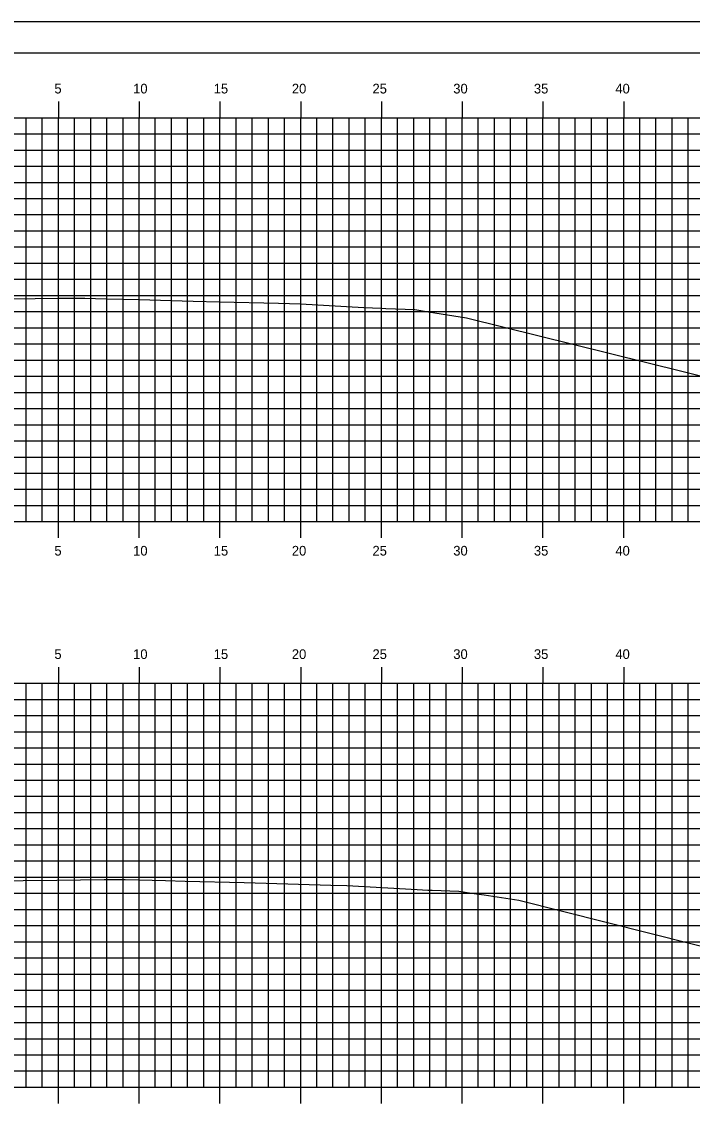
# Model space of a CAD drawing. Extents: x 1160718 to 1173142, y 616002 to 617630.
# Drawn here: x 1171295.7 to 1171337.2, y 616656.7 to 616723.9 of the extents above; entities that cross this region are included whole.
import ezdxf

# ---------------------------------------------------------------- set-up
doc = ezdxf.new("R2010")
doc.units = 0
for name, color, linetype in [('BORDER', 7, 'Continuous'), ('D_Roadway_SlopeLines', 7, 'Continuous'), ('H_V ANNOTATION', 7, 'Continuous'), ('MAJOR', 7, 'Continuous'), ('MINOR', 7, 'Continuous'), ('PLOT BOUNDARY', 7, 'Continuous'), ('S_Roadway_Centerline', 7, 'Continuous')]:
    doc.layers.add(name, color=color, linetype=linetype)

msp = doc.modelspace()

# ---------------------------------------------------------------- linework, layer by layer
at = {"layer": 'BORDER'}
msp.add_line((1171377.933, 616721.928), (1171217.933, 616721.928), dxfattribs=at)
at = {"layer": 'D_Roadway_SlopeLines'}
for points in [[(1171311.933, 616706.453), (1171312.022, 616706.431)], [(1171311.933, 616670.541), (1171312.029, 616670.517)]]:
    msp.add_lwpolyline(points, dxfattribs=at)
at = {"layer": 'MAJOR'}
for p, q in [((1171297.933, 616718.93), (1171297.933, 616717.928)), ((1171302.933, 616718.93), (1171302.933, 616717.928)), ((1171307.933, 616718.93), (1171307.933, 616717.928)), ((1171312.933, 616718.93), (1171312.933, 616717.928)), ((1171317.933, 616718.93), (1171317.933, 616717.928)), ((1171322.933, 616718.93), (1171322.933, 616717.928)), ((1171327.933, 616718.93), (1171327.933, 616717.928)), ((1171332.933, 616718.93), (1171332.933, 616717.928)), ((1171222.933, 616717.928), (1171362.933, 616717.928)), ((1171222.933, 616717.928), (1171362.933, 616717.928)), ((1171297.933, 616692.928), (1171297.933, 616717.928)), ((1171302.933, 616692.928), (1171302.933, 616717.928)), ((1171307.933, 616692.928), (1171307.933, 616717.928)), ((1171312.933, 616692.928), (1171312.933, 616717.928)), ((1171317.933, 616692.928), (1171317.933, 616717.928)), ((1171322.933, 616692.928), (1171322.933, 616717.928)), ((1171327.933, 616692.928), (1171327.933, 616717.928)), ((1171332.933, 616692.928), (1171332.933, 616717.928)), ((1171222.933, 616712.928), (1171362.933, 616712.928)), ((1171222.933, 616707.928), (1171362.933, 616707.928)), ((1171222.933, 616702.928), (1171362.933, 616702.928)), ((1171222.933, 616697.928), (1171362.933, 616697.928)), ((1171222.933, 616692.928), (1171362.933, 616692.928)), ((1171222.933, 616692.928), (1171362.933, 616692.928)), ((1171297.933, 616691.926), (1171297.933, 616692.928)), ((1171302.933, 616691.926), (1171302.933, 616692.928)), ((1171307.933, 616691.926), (1171307.933, 616692.928)), ((1171312.933, 616691.926), (1171312.933, 616692.928)), ((1171317.933, 616691.926), (1171317.933, 616692.928)), ((1171322.933, 616691.926), (1171322.933, 616692.928)), ((1171327.933, 616691.926), (1171327.933, 616692.928)), ((1171332.933, 616691.926), (1171332.933, 616692.928)), ((1171297.933, 616683.93), (1171297.933, 616682.928)), ((1171302.933, 616683.93), (1171302.933, 616682.928)), ((1171307.933, 616683.93), (1171307.933, 616682.928)), ((1171312.933, 616683.93), (1171312.933, 616682.928)), ((1171317.933, 616683.93), (1171317.933, 616682.928)), ((1171322.933, 616683.93), (1171322.933, 616682.928)), ((1171327.933, 616683.93), (1171327.933, 616682.928)), ((1171332.933, 616683.93), (1171332.933, 616682.928)), ((1171222.933, 616682.928), (1171362.933, 616682.928)), ((1171222.933, 616682.928), (1171362.933, 616682.928)), ((1171297.933, 616657.928), (1171297.933, 616682.928)), ((1171302.933, 616657.928), (1171302.933, 616682.928)), ((1171307.933, 616657.928), (1171307.933, 616682.928)), ((1171312.933, 616657.928), (1171312.933, 616682.928)), ((1171317.933, 616657.928), (1171317.933, 616682.928)), ((1171322.933, 616657.928), (1171322.933, 616682.928)), ((1171327.933, 616657.928), (1171327.933, 616682.928)), ((1171332.933, 616657.928), (1171332.933, 616682.928)), ((1171222.933, 616677.928), (1171362.933, 616677.928)), ((1171222.933, 616672.928), (1171362.933, 616672.928)), ((1171222.933, 616667.928), (1171362.933, 616667.928)), ((1171222.933, 616662.928), (1171362.933, 616662.928)), ((1171222.933, 616657.928), (1171362.933, 616657.928)), ((1171222.933, 616657.928), (1171362.933, 616657.928)), ((1171297.933, 616656.926), (1171297.933, 616657.928)), ((1171302.933, 616656.926), (1171302.933, 616657.928)), ((1171307.933, 616656.926), (1171307.933, 616657.928)), ((1171312.933, 616656.926), (1171312.933, 616657.928)), ((1171317.933, 616656.926), (1171317.933, 616657.928)), ((1171322.933, 616656.926), (1171322.933, 616657.928)), ((1171327.933, 616656.926), (1171327.933, 616657.928)), ((1171332.933, 616656.926), (1171332.933, 616657.928))]:
    msp.add_line(p, q, dxfattribs=at)
at = {"layer": 'MINOR'}
for p, q in [((1171295.933, 616692.928), (1171295.933, 616717.928)), ((1171296.933, 616692.928), (1171296.933, 616717.928)), ((1171298.933, 616692.928), (1171298.933, 616717.928)), ((1171299.933, 616692.928), (1171299.933, 616717.928)), ((1171300.933, 616692.928), (1171300.933, 616717.928)), ((1171301.933, 616692.928), (1171301.933, 616717.928)), ((1171303.933, 616692.928), (1171303.933, 616717.928)), ((1171304.933, 616692.928), (1171304.933, 616717.928)), ((1171305.933, 616692.928), (1171305.933, 616717.928)), ((1171306.933, 616692.928), (1171306.933, 616717.928)), ((1171308.933, 616692.928), (1171308.933, 616717.928)), ((1171309.933, 616692.928), (1171309.933, 616717.928)), ((1171310.933, 616692.928), (1171310.933, 616717.928)), ((1171311.933, 616692.928), (1171311.933, 616717.928)), ((1171313.933, 616692.928), (1171313.933, 616717.928)), ((1171314.933, 616692.928), (1171314.933, 616717.928)), ((1171315.933, 616692.928), (1171315.933, 616717.928)), ((1171316.933, 616692.928), (1171316.933, 616717.928)), ((1171318.933, 616692.928), (1171318.933, 616717.928)), ((1171319.933, 616692.928), (1171319.933, 616717.928)), ((1171320.933, 616692.928), (1171320.933, 616717.928)), ((1171321.933, 616692.928), (1171321.933, 616717.928)), ((1171323.933, 616692.928), (1171323.933, 616717.928)), ((1171324.933, 616692.928), (1171324.933, 616717.928)), ((1171325.933, 616692.928), (1171325.933, 616717.928)), ((1171326.933, 616692.928), (1171326.933, 616717.928)), ((1171328.933, 616692.928), (1171328.933, 616717.928)), ((1171329.933, 616692.928), (1171329.933, 616717.928)), ((1171330.933, 616692.928), (1171330.933, 616717.928)), ((1171331.933, 616692.928), (1171331.933, 616717.928)), ((1171333.933, 616692.928), (1171333.933, 616717.928)), ((1171334.933, 616692.928), (1171334.933, 616717.928)), ((1171335.933, 616692.928), (1171335.933, 616717.928)), ((1171336.933, 616692.928), (1171336.933, 616717.928)), ((1171222.933, 616716.928), (1171362.933, 616716.928)), ((1171222.933, 616715.928), (1171362.933, 616715.928)), ((1171222.933, 616714.928), (1171362.933, 616714.928)), ((1171222.933, 616713.928), (1171362.933, 616713.928)), ((1171222.933, 616711.928), (1171362.933, 616711.928)), ((1171222.933, 616710.928), (1171362.933, 616710.928)), ((1171222.933, 616709.928), (1171362.933, 616709.928)), ((1171222.933, 616708.928), (1171362.933, 616708.928)), ((1171222.933, 616706.928), (1171362.933, 616706.928)), ((1171222.933, 616705.928), (1171362.933, 616705.928)), ((1171222.933, 616704.928), (1171362.933, 616704.928)), ((1171222.933, 616703.928), (1171362.933, 616703.928)), ((1171222.933, 616701.928), (1171362.933, 616701.928)), ((1171222.933, 616700.928), (1171362.933, 616700.928)), ((1171222.933, 616699.928), (1171362.933, 616699.928)), ((1171222.933, 616698.928), (1171362.933, 616698.928)), ((1171222.933, 616696.928), (1171362.933, 616696.928)), ((1171222.933, 616695.928), (1171362.933, 616695.928)), ((1171222.933, 616694.928), (1171362.933, 616694.928)), ((1171222.933, 616693.928), (1171362.933, 616693.928)), ((1171295.933, 616657.928), (1171295.933, 616682.928)), ((1171296.933, 616657.928), (1171296.933, 616682.928)), ((1171298.933, 616657.928), (1171298.933, 616682.928)), ((1171299.933, 616657.928), (1171299.933, 616682.928)), ((1171300.933, 616657.928), (1171300.933, 616682.928)), ((1171301.933, 616657.928), (1171301.933, 616682.928)), ((1171303.933, 616657.928), (1171303.933, 616682.928)), ((1171304.933, 616657.928), (1171304.933, 616682.928)), ((1171305.933, 616657.928), (1171305.933, 616682.928)), ((1171306.933, 616657.928), (1171306.933, 616682.928)), ((1171308.933, 616657.928), (1171308.933, 616682.928)), ((1171309.933, 616657.928), (1171309.933, 616682.928)), ((1171310.933, 616657.928), (1171310.933, 616682.928)), ((1171311.933, 616657.928), (1171311.933, 616682.928)), ((1171313.933, 616657.928), (1171313.933, 616682.928)), ((1171314.933, 616657.928), (1171314.933, 616682.928)), ((1171315.933, 616657.928), (1171315.933, 616682.928)), ((1171316.933, 616657.928), (1171316.933, 616682.928)), ((1171318.933, 616657.928), (1171318.933, 616682.928)), ((1171319.933, 616657.928), (1171319.933, 616682.928)), ((1171320.933, 616657.928), (1171320.933, 616682.928)), ((1171321.933, 616657.928), (1171321.933, 616682.928)), ((1171323.933, 616657.928), (1171323.933, 616682.928)), ((1171324.933, 616657.928), (1171324.933, 616682.928)), ((1171325.933, 616657.928), (1171325.933, 616682.928)), ((1171326.933, 616657.928), (1171326.933, 616682.928)), ((1171328.933, 616657.928), (1171328.933, 616682.928)), ((1171329.933, 616657.928), (1171329.933, 616682.928)), ((1171330.933, 616657.928), (1171330.933, 616682.928)), ((1171331.933, 616657.928), (1171331.933, 616682.928)), ((1171333.933, 616657.928), (1171333.933, 616682.928)), ((1171334.933, 616657.928), (1171334.933, 616682.928)), ((1171335.933, 616657.928), (1171335.933, 616682.928)), ((1171336.933, 616657.928), (1171336.933, 616682.928)), ((1171222.933, 616681.928), (1171362.933, 616681.928)), ((1171222.933, 616680.928), (1171362.933, 616680.928)), ((1171222.933, 616679.928), (1171362.933, 616679.928)), ((1171222.933, 616678.928), (1171362.933, 616678.928)), ((1171222.933, 616676.928), (1171362.933, 616676.928)), ((1171222.933, 616675.928), (1171362.933, 616675.928)), ((1171222.933, 616674.928), (1171362.933, 616674.928)), ((1171222.933, 616673.928), (1171362.933, 616673.928)), ((1171222.933, 616671.928), (1171362.933, 616671.928)), ((1171222.933, 616670.928), (1171362.933, 616670.928)), ((1171222.933, 616669.928), (1171362.933, 616669.928)), ((1171222.933, 616668.928), (1171362.933, 616668.928)), ((1171222.933, 616666.928), (1171362.933, 616666.928)), ((1171222.933, 616665.928), (1171362.933, 616665.928)), ((1171222.933, 616664.928), (1171362.933, 616664.928)), ((1171222.933, 616663.928), (1171362.933, 616663.928)), ((1171222.933, 616661.928), (1171362.933, 616661.928)), ((1171222.933, 616660.928), (1171362.933, 616660.928)), ((1171222.933, 616659.928), (1171362.933, 616659.928)), ((1171222.933, 616658.928), (1171362.933, 616658.928))]:
    msp.add_line(p, q, dxfattribs=at)
at = {"layer": 'PLOT BOUNDARY'}
msp.add_lwpolyline([(1171209.84, 616613.869), (1171379.84, 616613.869), (1171379.84, 616723.869), (1171209.84, 616723.869)], close=True, dxfattribs=at)
at = {"layer": 'S_Roadway_Centerline'}
for points in [[(1171295.094, 616706.726), (1171297.896, 616706.763), (1171298.536, 616706.759), (1171299.575, 616706.754), (1171300.882, 616706.72), (1171302.903, 616706.667), (1171306.283, 616706.581), (1171307.91, 616706.54), (1171311.563, 616706.443), (1171312.916, 616706.407), (1171316.846, 616706.19), (1171317.923, 616706.131), (1171318.214, 616706.121), (1171320.004, 616706.06), (1171320.846, 616705.92), (1171323.21, 616705.54), (1171341.027, 616701.118), (1171347.742, 616699.546), (1171362.933, 616699.208)], [(1171293.122, 616670.667), (1171295.756, 616670.712), (1171297.835, 616670.739), (1171300.766, 616670.777), (1171301.571, 616670.778), (1171302.057, 616670.78), (1171304.559, 616670.715), (1171305.776, 616670.682), (1171309.444, 616670.588), (1171310.786, 616670.554), (1171314.796, 616670.435), (1171315.796, 616670.406), (1171320.15, 616670.157), (1171320.806, 616670.119), (1171321.079, 616670.11), (1171322.733, 616670.052), (1171323.513, 616669.938), (1171324.289, 616669.825), (1171326.442, 616669.495), (1171342.576, 616665.438), (1171350.449, 616663.486), (1171362.933, 616662.972)]]:
    msp.add_lwpolyline(points, dxfattribs=at)

# ---------------------------------------------------------------- texts
at = {"layer": 'H_V ANNOTATION'}
for s, p in [('5', (1171297.684, 616719.428)), ('10', (1171302.559, 616719.428)), ('15', (1171307.551, 616719.428)), ('20', (1171312.387, 616719.428)), ('25', (1171317.379, 616719.428)), ('30', (1171322.382, 616719.428)), ('35', (1171327.374, 616719.428)), ('40', (1171332.419, 616719.428)), ('5', (1171297.684, 616690.828)), ('10', (1171302.559, 616690.828)), ('15', (1171307.551, 616690.828)), ('20', (1171312.387, 616690.828)), ('25', (1171317.379, 616690.828)), ('30', (1171322.382, 616690.828)), ('35', (1171327.374, 616690.828)), ('40', (1171332.419, 616690.828)), ('5', (1171297.684, 616684.428)), ('10', (1171302.559, 616684.428)), ('15', (1171307.551, 616684.428)), ('20', (1171312.387, 616684.428)), ('25', (1171317.379, 616684.428)), ('30', (1171322.382, 616684.428)), ('35', (1171327.374, 616684.428)), ('40', (1171332.419, 616684.428))]:
    msp.add_text(s, height=0.6, dxfattribs=at).set_placement(p)

doc.saveas('drawing.dxf')
